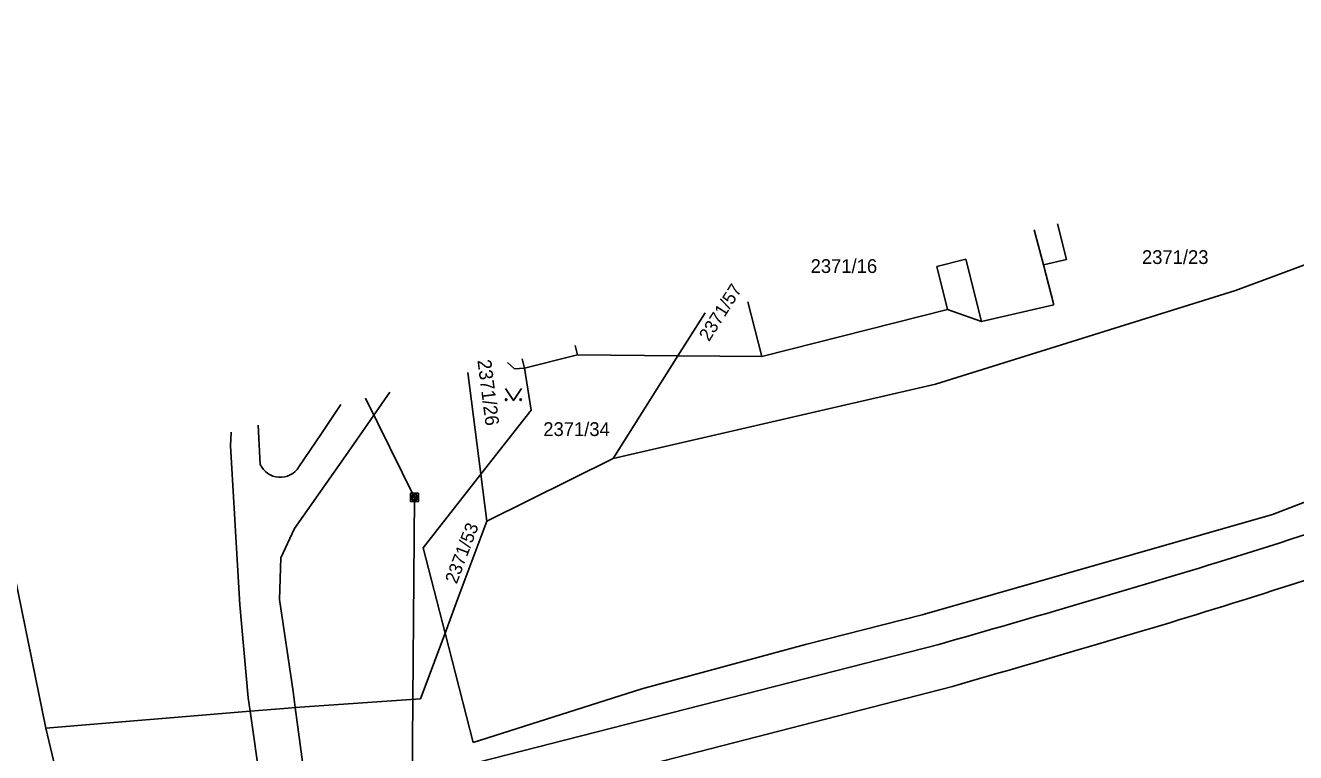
# Model space of a CAD drawing. Extents: x -825057 to -819383, y -1071633 to -1067888.
# Drawn here: x -820385.6 to -820228.7, y -1069558.7 to -1069468.9 of the extents above; entities that cross this region are included whole.
import ezdxf

# ---------------------------------------------------------------- set-up
doc = ezdxf.new("R2010")
doc.units = 0
for name, color, linetype in [('Vrstva 1', 7, 'Continuous'), ('Vrstva 10', 7, 'Continuous'), ('Vrstva 12', 7, 'Continuous'), ('Vrstva 18', 7, 'Continuous'), ('Vrstva 19', 7, 'Continuous'), ('Vrstva 25', 7, 'Continuous'), ('Vrstva 26', 7, 'Continuous'), ('Vrstva 4', 7, 'Continuous')]:
    doc.layers.add(name, color=color, linetype=linetype)

msp = doc.modelspace()

# ---------------------------------------------------------------- linework, layer by layer
at = {"layer": 'Vrstva 1'}
for p, q in [((-820196.03, -1069486.83), (-820236.1, -1069501.64)), ((-820260.96, -1069494.16), (-820259.83, -1069498.5)), ((-820256.98, -1069497.83), (-820258.1, -1069493.44)), ((-820259.83, -1069498.5), (-820256.98, -1069497.83)), ((-820258.55, -1069503.41), (-820259.83, -1069498.5)), ((-820236.1, -1069501.64), (-820273.14, -1069513.21)), ((-820304.98, -1069509.72), (-820301.61, -1069504.39)), ((-820294.62, -1069509.81), (-820296.34, -1069503.06)), ((-820294.62, -1069509.81), (-820271.67, -1069503.99)), ((-820271.67, -1069503.99), (-820267.47, -1069505.48)), ((-820267.47, -1069505.48), (-820258.55, -1069503.41)), ((-820317.68, -1069508.43), (-820317.39, -1069509.61)), ((-820324.22, -1069510.08), (-820323.93, -1069511.24)), ((-820317.39, -1069509.61), (-820323.93, -1069511.24)), ((-820317.39, -1069509.61), (-820304.98, -1069509.72)), ((-820312.98, -1069522.39), (-820304.98, -1069509.72)), ((-820304.98, -1069509.72), (-820294.62, -1069509.81)), ((-820330.94, -1069511.77), (-820329.33, -1069524.3)), ((-820323.93, -1069511.24), (-820323.13, -1069516.42)), ((-820273.14, -1069513.21), (-820312.98, -1069522.39)), ((-820323.13, -1069516.42), (-820329.33, -1069524.3)), ((-820360.17, -1069519.13), (-820360.24, -1069520.83)), ((-820360.24, -1069520.83), (-820359.09, -1069540.44)), ((-820312.98, -1069522.39), (-820328.58, -1069530.12)), ((-820329.33, -1069524.3), (-820336.47, -1069533.39)), ((-820329.33, -1069524.3), (-820328.58, -1069530.12)), ((-820389.08, -1069526.4), (-820383.05, -1069555.68)), ((-820328.58, -1069530.12), (-820332.15, -1069539.66)), ((-820336.47, -1069533.39), (-820333.75, -1069543.93)), ((-820359.09, -1069540.44), (-820358.08, -1069551.91)), ((-820332.15, -1069539.66), (-820333.75, -1069543.93)), ((-820333.75, -1069543.93), (-820336.79, -1069552.05)), ((-820358.08, -1069551.91), (-820357.83, -1069553.58)), ((-820336.79, -1069552.05), (-820352.25, -1069553.13)), ((-820357.83, -1069553.58), (-820383.05, -1069555.68)), ((-820353.12, -1069553.19), (-820357.83, -1069553.58)), ((-820352.25, -1069553.13), (-820353.12, -1069553.19)), ((-820383.05, -1069555.68), (-820379.33, -1069571.23))]:
    msp.add_line(p, q, dxfattribs=at)
at = {"layer": 'Vrstva 10'}
for p, q in [((-820272.75, -1069545.33), (-820396.61, -1069576.94)), ((-820395.38, -1069582.43), (-820271.07, -1069550.51))]:
    msp.add_line(p, q, dxfattribs=at)
for points in [[(-819936.83, -1069349.47), (-819975.71, -1069383.16), (-819999.35, -1069402.16), (-820038.47, -1069432.26), (-820078.04, -1069460.09), (-820109.89, -1069479.65), (-820134.7, -1069493.27), (-820163.02, -1069506.83), (-820195.64, -1069520.53), (-820237.28, -1069534.88), (-820272.75, -1069545.33)], [(-820271.07, -1069550.51), (-820235.31, -1069539.9), (-820193.69, -1069525.37), (-820161.56, -1069511.74), (-820132.38, -1069497.54), (-820107.7, -1069483.92), (-820075.84, -1069464.22), (-820035.7, -1069436.13), (-819996.53, -1069406.13), (-819972.84, -1069386.82), (-819933.47, -1069352.83)]]:
    msp.add_spline(points, degree=3, dxfattribs=at)
at = {"layer": 'Vrstva 12'}
for p, q in [((-820343.59, -1069514.95), (-820337.52, -1069527.18)), ((-820337.52, -1069527.18), (-820338.4, -1069631.72))]:
    msp.add_line(p, q, dxfattribs=at)
at = {"layer": 'Vrstva 25'}
msp.add_lwpolyline([(-820324.3, -1069513.73), (-820325.3, -1069515.23), (-820326.3, -1069513.73)], dxfattribs=at)
for centre in [(-820326.2, -1069515.13), (-820324.4, -1069515.13)]:
    msp.add_circle(centre, 0.1, dxfattribs=at)
at = {"layer": 'Vrstva 26'}
for points in [[(-820337.02, -1069526.68), (-820338.02, -1069526.68), (-820338.02, -1069527.68), (-820337.02, -1069527.68)], [(-820337.22, -1069526.88), (-820337.82, -1069526.88), (-820337.82, -1069527.48), (-820337.22, -1069527.48)], [(-820337.62, -1069527.28), (-820337.42, -1069527.28), (-820337.42, -1069527.08), (-820337.62, -1069527.08)]]:
    msp.add_lwpolyline(points, close=True, dxfattribs=at)
at = {"layer": 'Vrstva 4'}
for p, q in [((-820273, -1069498.67), (-820269.4, -1069497.77)), ((-820269.4, -1069497.77), (-820267.47, -1069505.48)), ((-820271.67, -1069503.99), (-820273, -1069498.67)), ((-820326.02, -1069510.53), (-820325.18, -1069511.33)), ((-820325.18, -1069511.33), (-820323.93, -1069511.24)), ((-820345.71, -1069521.62), (-820340.55, -1069514.19)), ((-820346.63, -1069515.72), (-820349.02, -1069519.28)), ((-820356.57, -1069523.12), (-820356.83, -1069518.28)), ((-820349.02, -1069519.28), (-820351.81, -1069523.43)), ((-820352.33, -1069531.04), (-820345.71, -1069521.62)), ((-820211.97, -1069521.69), (-820231.53, -1069529.3)), ((-820231.53, -1069529.3), (-820274.81, -1069541.66)), ((-820354.03, -1069534.64), (-820352.33, -1069531.04)), ((-820354.22, -1069539.77), (-820354.03, -1069534.64)), ((-820352.52, -1069551.14), (-820354.22, -1069539.77)), ((-820274.81, -1069541.66), (-820289.2, -1069545.34)), ((-820330.27, -1069557.45), (-820333.75, -1069543.93)), ((-820289.2, -1069545.34), (-820309.42, -1069550.8)), ((-820352.25, -1069553.13), (-820352.52, -1069551.14)), ((-820309.42, -1069550.8), (-820330.27, -1069557.45)), ((-820356.09, -1069565.59), (-820357.83, -1069553.58)), ((-820352.25, -1069553.13), (-820350.74, -1069564.3))]:
    msp.add_line(p, q, dxfattribs=at)
msp.add_arc((-820354.108, -1069522.013), 2.699, 204.20287, 328.34476, dxfattribs=at)

# ---------------------------------------------------------------- texts
at = {"layer": 'Vrstva 18'}
for s, p in [('2371/23', (-820247.656, -1069498.38)), ('2371/34', (-820321.612, -1069519.61))]:
    msp.add_text(s, height=1.7, dxfattribs=at).set_placement(p)
for s, height, rotation, p in [('2371/57', 1.6, 57.6, (-820301.14, -1069508.033)), ('2371/26', 1.7, 277.2, (-820329.755, -1069510.272)), ('2371/53', 1.6, 69.3, (-820332.309, -1069537.947))]:
    msp.add_text(s, height=height, rotation=rotation, dxfattribs=at).set_placement(p)
at = {"layer": 'Vrstva 19'}
msp.add_text('2371/16', height=1.7, dxfattribs=at).set_placement((-820288.588, -1069499.49))

doc.saveas('drawing.dxf')
